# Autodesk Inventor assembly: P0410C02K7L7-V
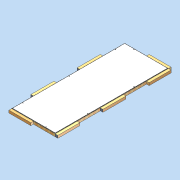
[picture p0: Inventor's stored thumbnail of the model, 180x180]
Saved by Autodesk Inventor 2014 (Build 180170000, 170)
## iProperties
Created: 2011-04
Part Number: P0410C02K7L7-V
Document SubType Name: Assembly
Designer: david.appleford
Mass: 66000 g
Surface Area: 87307.4 cm^2
Volume: 302911 cm^3
Density: 0.217886 g/cm^3
Cost Center: £209.00
Description: 1w x 2.5w 02 Ceiling Panel 7 Locks 7 Lugs
Justset: False
Author: david.appleford
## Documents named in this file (4)
- C:\Documents and Settings\john.everitt\Local Settings\My Documents\Vault\Production MkII\VIRTUAL ELEMENTS\Virtual Ceilings\Ceiling MgO & Timber Frame\P0410C02K7L7-V.iam
- C:\Documents and Settings\john.everitt\Local Settings\My Documents\Vault\Production MkII\VIRTUAL ELEMENTS\Virtual Lugs\Superceded Lugs\LA02C3V.ipt
- C:\Documents and Settings\john.everitt\Local Settings\My Documents\Vault\Production MkII\VIRTUAL ELEMENTS\Virtual Lugs\Superceded Lugs\LA02M3V.ipt
- C:\Documents and Settings\john.everitt\Local Settings\My Documents\Vault\Production MkII\VIRTUAL ELEMENTS\Virtual Ceilings\Ceiling MgO & Timber Frame\P0410C02K7-V.ipt
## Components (8 placed, 3 different names)
1. P0410C02K7-V:1 — Mate:1, Flush:1, Flush:2, Mate:2, Flush:3, Flush:4, Mate:4, Flush:7, Flush:8, Mate:5, Mate:6, Flush:9, Flush:10, Mate:7, Mate:8, Flush:11, Flush:12
2. LA02C3V:1 — Mate:1, Flush:1, Flush:2, Mate:9, Mate:13
3. LA02C3V:2 — Mate:2, Flush:3, Flush:4
4. LA02C3V:3 — Mate:4, Flush:7, Flush:8
5. LA02M3V:1 — Mate:6, Flush:9, Mate:12
6. LA02M3V:2 — Mate:5, Flush:10, Mate:12, Mate:13
7. LA02C3V:4 — Mate:8, Flush:12, Mate:10
8. LA02M3V:4 — Mate:7, Flush:11, Mate:9, Mate:10
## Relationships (21: Mate 11, Flush 10)
- Mate:1: P0410C02K7-V:1 ↔ LA02C3V:1
- Flush:1: P0410C02K7-V:1 ↔ LA02C3V:1
- Flush:2: P0410C02K7-V:1 ↔ LA02C3V:1
- Mate:2: P0410C02K7-V:1 ↔ LA02C3V:2
- Flush:3: P0410C02K7-V:1 ↔ LA02C3V:2
- Flush:4: P0410C02K7-V:1 ↔ LA02C3V:2
- Mate:4: P0410C02K7-V:1 ↔ LA02C3V:3
- Flush:7: P0410C02K7-V:1 ↔ LA02C3V:3
- Flush:8: P0410C02K7-V:1 ↔ LA02C3V:3
- Mate:5: P0410C02K7-V:1 ↔ LA02M3V:2
- Mate:6: P0410C02K7-V:1 ↔ LA02M3V:1
- Flush:9: P0410C02K7-V:1 ↔ LA02M3V:1
- Flush:10: P0410C02K7-V:1 ↔ LA02M3V:2
- Mate:7: P0410C02K7-V:1 ↔ LA02M3V:4
- Mate:8: P0410C02K7-V:1 ↔ LA02C3V:4
- Flush:11: P0410C02K7-V:1 ↔ LA02M3V:4
- Flush:12: P0410C02K7-V:1 ↔ LA02C3V:4
- Mate:9: LA02C3V:1 ↔ LA02M3V:4
- Mate:10: LA02C3V:4 ↔ LA02M3V:4
- Mate:12: LA02M3V:1 ↔ LA02M3V:2
- Mate:13: LA02C3V:1 ↔ LA02M3V:2
## Named parameters: t = 1 mm, Cl = 2 mm
